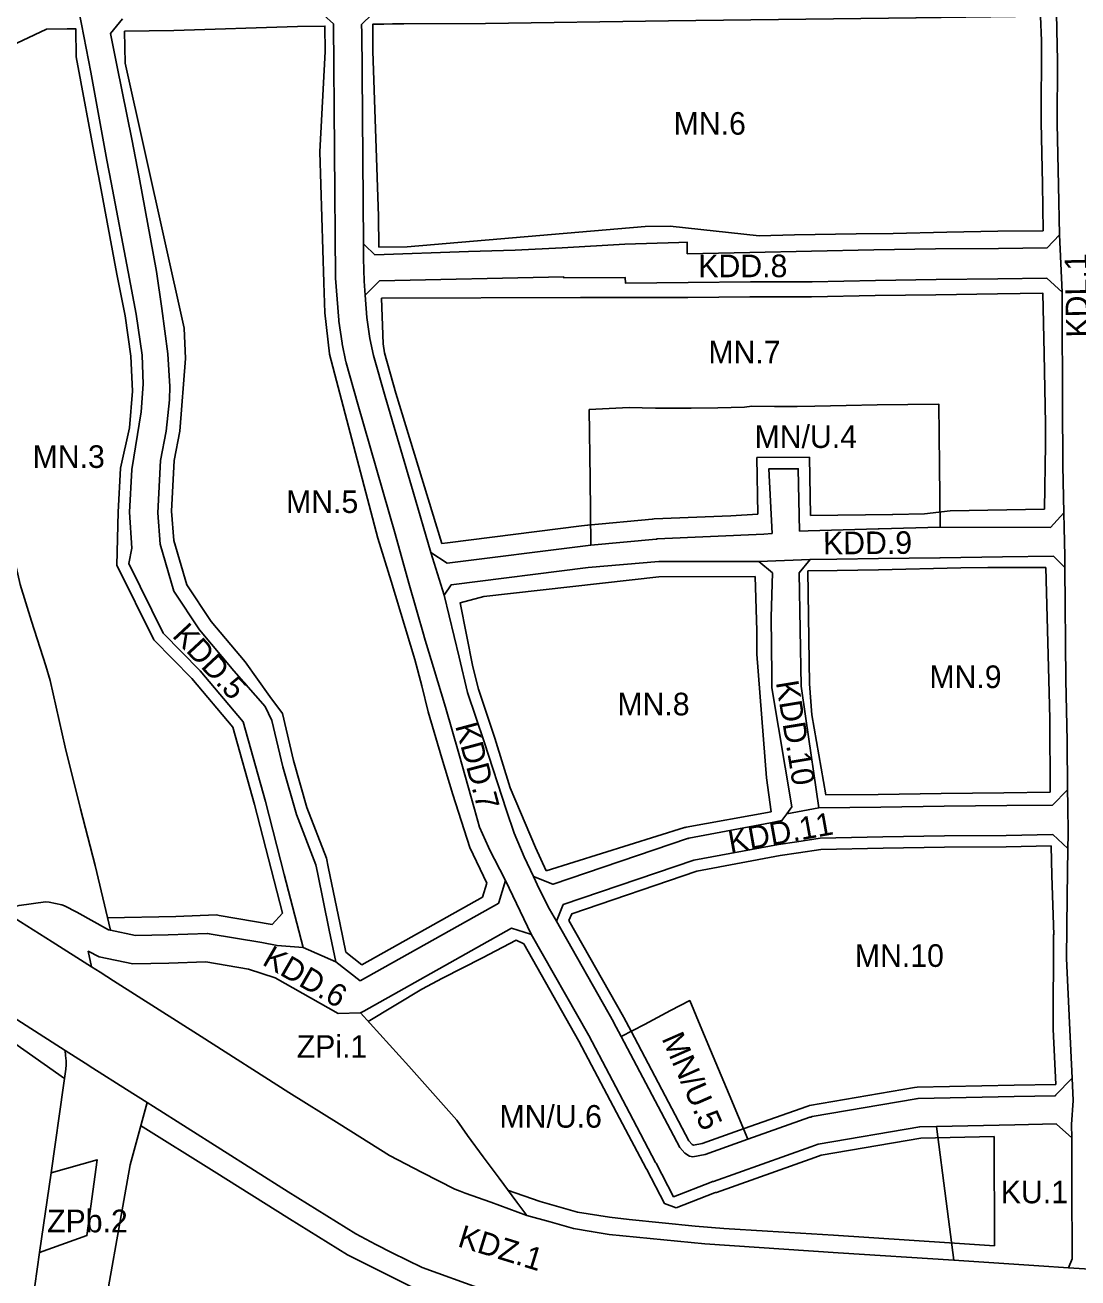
# Model space of a CAD drawing. Extents: x 7431080 to 7433370, y 5546450 to 5548428.
# Drawn here: x 7431280.3 to 7431653, y 5546842.9 to 5547286.3 of the extents above; entities that cross this region are included whole.
import ezdxf

# ---------------------------------------------------------------- set-up
doc = ezdxf.new("R2010")
doc.units = 0
for name, color, linetype in [('Linie Rozgraniczajace', 7, 'Continuous'), ('nieprzekraczalna linia zabudowy', 7, 'Continuous'), ('oznaczenia_przeznaczen', 7, 'Continuous')]:
    doc.layers.add(name, color=color, linetype=linetype)

msp = doc.modelspace()

# ---------------------------------------------------------------- linework, layer by layer
at = {"layer": 'Linie Rozgraniczajace'}
for p, q in [((7431503.72, 5547104.41), (7431480.6, 5547102.28)), ((7431541.78, 5547106.21), (7431544.79, 5547106.35)), ((7431428.7, 5547084.51), (7431424.02, 5547099.63)), ((7431544.96, 5547092.47), (7431540.08, 5547096.48)), ((7431546.99, 5546996.37), (7431553.47, 5546997.31)), ((7431285.51, 5546851.9), (7431289.57, 5546880.06)), ((7431457.94, 5546865.03), (7431445.21, 5546869.68)), ((7431457.94, 5546865.03), (7431454.46, 5546869.71))]:
    msp.add_line(p, q, dxfattribs=at)
for points in [[(7431390.34, 5546954.83), (7431378.8, 5546959.84), (7431372.11, 5546985.69), (7431365.42, 5547011.53), (7431357.5, 5547039.75), (7431342.29, 5547057.75), (7431329.25, 5547071.13), (7431317.06, 5547095.73), (7431318.2, 5547101.16), (7431317.29, 5547113.99), (7431318.15, 5547129.1), (7431321.47, 5547149.42), (7431322.16, 5547159.21), (7431321.76, 5547169.51), (7431319.7, 5547184.04), (7431316.79, 5547198.96), (7431310.88, 5547230.65), (7431309.31, 5547238.54), (7431303.61, 5547269.63), (7431300.27, 5547286.7), (7431297.91, 5547298.79)], [(7431400.09, 5547208.92), (7431399.5, 5547284.55), (7431399.48, 5547285.56), (7431399.47, 5547286.56), (7431403.16, 5547290.15), (7431404.45, 5547290.17), (7431443.28, 5547290.86), (7431508.06, 5547291.84), (7431608.94, 5547294.01), (7431608.98, 5547294.02), (7431609.02, 5547294.01), (7431640.93, 5547295.19), (7431645.37, 5547290.69)], [(7431646.11, 5547229.52), (7431645.64, 5547251.49), (7431645.76, 5547273.63), (7431645.5, 5547284.65), (7431645.37, 5547290.69), (7431645.25, 5547295.66)], [(7431398.93, 5546948.02), (7431390.34, 5546954.83), (7431388.02, 5546966.06), (7431383.82, 5546986.4), (7431383.27, 5546989.15), (7431376.44, 5547006.94), (7431371.63, 5547023.83), (7431367.75, 5547040.21), (7431365.33, 5547045.19), (7431354.3, 5547057.83), (7431342.1, 5547072.28), (7431333.03, 5547086.03), (7431328.12, 5547102.65), (7431327.33, 5547113.76), (7431328.29, 5547132.24), (7431330.29, 5547142.66), (7431331.52, 5547153.75), (7431331.59, 5547158.37), (7431330.89, 5547170.02), (7431328.77, 5547186.07), (7431326.91, 5547199.12), (7431320.7, 5547232.54), (7431318.12, 5547245.95), (7431312.95, 5547271.59), (7431310.62, 5547283.33), (7431314.85, 5547288.59)], [(7431411.39, 5547106.3), (7431398.16, 5547152.21), (7431393.99, 5547166.85), (7431393.97, 5547167.03), (7431393.91, 5547167.2), (7431392.59, 5547173.5), (7431392.56, 5547173.72), (7431392.54, 5547173.81), (7431391.42, 5547181.59), (7431391.4, 5547181.85), (7431391.39, 5547181.88), (7431390.2, 5547196.73), (7431390.22, 5547196.91), (7431390.18, 5547197.1), (7431389.5, 5547286.74), (7431386.05, 5547289.82), (7431403.16, 5547290.15)], [(7431310.57, 5546966), (7431305.12, 5546988.88), (7431299.98, 5547008.9), (7431294.56, 5547030.81), (7431289.26, 5547054.34), (7431287.66, 5547059.57), (7431282.62, 5547075.34), (7431278.58, 5547088.36), (7431271.49, 5547119.64), (7431263.97, 5547139.42), (7431263.95, 5547139.47), (7431244.76, 5547197.76), (7431231.95, 5547265)], [(7431648.18, 5547108.5), (7431648.07, 5547113.72), (7431647.72, 5547130.39), (7431647.54, 5547152.86), (7431647.49, 5547163.89), (7431647.43, 5547174.92), (7431647.4, 5547185.89), (7431647.38, 5547191.85), (7431646.45, 5547212.12), (7431646.11, 5547229.52)], [(7431492.6, 5547208.74), (7431511.75, 5547209.35), (7431514.75, 5547209.45), (7431514.73, 5547205.42), (7431536.92, 5547205.81), (7431558.76, 5547206.33), (7431580.81, 5547206.76), (7431602.65, 5547207.19), (7431624.84, 5547207.27), (7431642.14, 5547207.51), (7431646.45, 5547212.12)], [(7431400.71, 5547190.73), (7431400.32, 5547195.71), (7431400.11, 5547203.69), (7431400.09, 5547208.92)], [(7431400.09, 5547208.92), (7431400.51, 5547208.51), (7431404.16, 5547204.97), (7431437.36, 5547206.25), (7431453.84, 5547206.63), (7431470.45, 5547207.53), (7431492.6, 5547208.74)], [(7431400.71, 5547190.73), (7431400.91, 5547190.93), (7431405.79, 5547195.79), (7431471.03, 5547197.23)], [(7431515.07, 5547195.25), (7431492.88, 5547194.94), (7431492.72, 5547197.04), (7431471.07, 5547196.85), (7431471.03, 5547197.23)], [(7431515.07, 5547195.25), (7431537.09, 5547195.5), (7431558.9, 5547195.48), (7431581.31, 5547195.97), (7431602.88, 5547196.25), (7431624.71, 5547196.55), (7431641.99, 5547196.79), (7431647.38, 5547191.85)], [(7431424.02, 5547099.63), (7431417.73, 5547121.08), (7431407.79, 5547154.92), (7431403.66, 5547169.41), (7431402.41, 5547175.39), (7431401.35, 5547182.84), (7431400.71, 5547190.73)], [(7431480.6, 5547102.28), (7431480.34, 5547125.71), (7431480.07, 5547150.23), (7431487.1, 5547150.58), (7431494.13, 5547150.94), (7431498.83, 5547150.86), (7431503.53, 5547150.78)], [(7431503.53, 5547150.78), (7431509.81, 5547150.79), (7431516.09, 5547150.79), (7431525.54, 5547150.92), (7431534.98, 5547151.06), (7431537.56, 5547151.42), (7431545.61, 5547151.36), (7431553.65, 5547151.29), (7431559.93, 5547151.51), (7431570.94, 5547151.73), (7431581.95, 5547151.94), (7431592.84, 5547152.08), (7431603.74, 5547152.22), (7431604.02, 5547130.41), (7431604.3, 5547108.6)], [(7431554.49, 5547107.26), (7431554.03, 5547129.33), (7431543.62, 5547129.29), (7431544.79, 5547106.35)], [(7431648.07, 5547113.72), (7431643.36, 5547108.52)], [(7431411.39, 5547106.3), (7431416.14, 5547088.8), (7431421.57, 5547069.98), (7431421.61, 5547069.89), (7431421.61, 5547069.84), (7431424.93, 5547058.94), (7431429.14, 5547044.98), (7431433.92, 5547028.53), (7431439.46, 5547008.85), (7431441.25, 5547002.47), (7431444.34, 5546995.39), (7431444.51, 5546994.98), (7431450.36, 5546983.54), (7431459.52, 5546964.61)], [(7431503.72, 5547104.41), (7431503.83, 5547104.43), (7431504.14, 5547104.45), (7431541.78, 5547106.21)], [(7431554.49, 5547107.26), (7431557.5, 5547107.38)], [(7431643.36, 5547108.52), (7431604.3, 5547108.6), (7431582.62, 5547108.1), (7431582.49, 5547108.06), (7431582.34, 5547108.09), (7431557.5, 5547107.38)], [(7431648.36, 5547098.4), (7431648.18, 5547108.5)], [(7431424.02, 5547099.63), (7431429.76, 5547095.85), (7431478.7, 5547102.04), (7431480.6, 5547102.28)], [(7431428.7, 5547084.51), (7431431.12, 5547088.2), (7431479.68, 5547094.34), (7431504.72, 5547096.49), (7431540.08, 5547096.48), (7431558.22, 5547097.2)], [(7431555.03, 5547052.32), (7431554.39, 5547092.47), (7431558.22, 5547097.2), (7431567.72, 5547097.32), (7431582.38, 5547097.51), (7431604.15, 5547097.81), (7431604.19, 5547097.82), (7431604.24, 5547097.81), (7431626.37, 5547098.16), (7431644.41, 5547098.36)], [(7431644.41, 5547098.36), (7431648.39, 5547094.41)], [(7431649.38, 5547010.34), (7431649.33, 5547015.66), (7431649.17, 5547033.04), (7431648.67, 5547054.45), (7431648.39, 5547094.41), (7431648.36, 5547098.4)], [(7431550.01, 5547007.23), (7431551.79, 5547009.66), (7431544.67, 5547051.76), (7431544.62, 5547056.26), (7431544.45, 5547076.82), (7431544.96, 5547092.47)], [(7431460.29, 5546984.95), (7431456.98, 5546991.98), (7431453.47, 5547000.31), (7431450.77, 5547008.35), (7431442.84, 5547032.7), (7431436.97, 5547050.15), (7431433.97, 5547062.6), (7431428.7, 5547084.51)], [(7431555.03, 5547052.32), (7431556.7, 5547040.93), (7431561.36, 5547009.28), (7431583.28, 5547009.52), (7431605.62, 5547009.86), (7431627.84, 5547010.07), (7431644.01, 5547010.27), (7431649.33, 5547015.66)], [(7431561.36, 5547009.28), (7431550.01, 5547007.23), (7431548.22, 5547004.8), (7431544.15, 5547004.03)], [(7431649.55, 5546999.94), (7431649.38, 5547010.34)], [(7431460.29, 5546984.95), (7431467.18, 5546982.3), (7431467.25, 5546982.26), (7431514.79, 5546998.4), (7431515.02, 5546998.44), (7431515.32, 5546998.54), (7431544.15, 5547004.03)], [(7431561.73, 5546998.51), (7431553.47, 5546997.31)], [(7431649.48, 5546994.88), (7431644.12, 5546999.82), (7431627.57, 5546999.45), (7431605.73, 5546999.43), (7431583.97, 5546999.01), (7431561.73, 5546998.51)], [(7431650.03, 5546933.21), (7431648.99, 5546956.02), (7431649.25, 5546977.86), (7431649.27, 5546977.94), (7431649.25, 5546978.01), (7431649.48, 5546994.88), (7431649.55, 5546999.94)], [(7431468.43, 5546969.18), (7431470.87, 5546975.05), (7431517.1, 5546990.73), (7431546.99, 5546996.37)], [(7431468.43, 5546969.18), (7431466.02, 5546973.4), (7431462.31, 5546980.59), (7431462.34, 5546980.6), (7431460.29, 5546984.95)], [(7431450.36, 5546983.54), (7431447.99, 5546975.82), (7431448, 5546975.6), (7431398.93, 5546948.02)], [(7431262.98, 5546978.9), (7431272.03, 5546973.18), (7431278.23, 5546974.79), (7431287.58, 5546976.08), (7431288.88, 5546975.96), (7431293.32, 5546974.95), (7431294.31, 5546974.63), (7431298.65, 5546972.4)], [(7431272.03, 5546973.18), (7431289.89, 5546961.88), (7431303.9, 5546953.02), (7431306.93, 5546951.1), (7431311.64, 5546948.1)], [(7431378.8, 5546959.84), (7431369.61, 5546960.62), (7431364.21, 5546961.58), (7431345.54, 5546964.73), (7431344.94, 5546964.83), (7431330.95, 5546964.34), (7431319.48, 5546964.08), (7431310.57, 5546966), (7431309.93, 5546966.14), (7431298.65, 5546972.4)], [(7431491.33, 5546928.35), (7431488.63, 5546933.41), (7431488.58, 5546933.53), (7431468.43, 5546969.18)], [(7431399.08, 5546936.72), (7431400, 5546937.17), (7431400.26, 5546937.3), (7431452.53, 5546966.68), (7431459.29, 5546964.63), (7431459.52, 5546964.61), (7431479.84, 5546928.67), (7431494.3, 5546901.3)], [(7431399.08, 5546936.72), (7431391.14, 5546936.51), (7431368.86, 5546949.18), (7431359.43, 5546952.24), (7431344.28, 5546954.8), (7431331.24, 5546954.34), (7431318.53, 5546954.06), (7431306.63, 5546956.62), (7431302.74, 5546958.53), (7431303.9, 5546953.02)], [(7431304.29, 5546917.19), (7431301.62, 5546918.88), (7431294.52, 5546923.41), (7431276.16, 5546935.16), (7431257.57, 5546947.05), (7431250.17, 5546951.65), (7431242.76, 5546956.25), (7431240.39, 5546957.73)], [(7431311.64, 5546948.1), (7431342.65, 5546928.35), (7431373.66, 5546908.6), (7431391.53, 5546897.41), (7431409.39, 5546886.22), (7431420.95, 5546880.27), (7431432.51, 5546874.32), (7431434.32, 5546873.63), (7431436.13, 5546872.95), (7431445.21, 5546869.68)], [(7431536.21, 5546891.99), (7431529.54, 5546907.88), (7431522.98, 5546923.5), (7431519.29, 5546932.29), (7431515.59, 5546941.07), (7431508.85, 5546937.53), (7431499.57, 5546932.67), (7431491.33, 5546928.35)], [(7431454.46, 5546869.71), (7431448.13, 5546878.23), (7431442.53, 5546885.77), (7431436.93, 5546893.31), (7431433.23, 5546898.79), (7431416.16, 5546917.84), (7431399.08, 5546936.72)], [(7431650.87, 5546879.8), (7431650.84, 5546892.51), (7431650.79, 5546897.2), (7431651.28, 5546905.74), (7431650.92, 5546913.64), (7431650.03, 5546933.21)], [(7431536.21, 5546891.99), (7431521.07, 5546886.62), (7431516.7, 5546885.83), (7431515.54, 5546886.04), (7431513.91, 5546887.13), (7431512.06, 5546889.09), (7431491.33, 5546928.35)], [(7431294.52, 5546923.41), (7431294.7, 5546921.59), (7431294.89, 5546919.77), (7431294.86, 5546918.31), (7431294.83, 5546916.85), (7431293.98, 5546910.98)], [(7431304.29, 5546917.19), (7431316.25, 5546909.61), (7431323.53, 5546904.99)], [(7431650.92, 5546913.64), (7431645.11, 5546907.57), (7431645.05, 5546907.41), (7431630.47, 5546907.12), (7431596.46, 5546906.4), (7431596.42, 5546906.39), (7431596.37, 5546906.4), (7431595.72, 5546906.33), (7431558.97, 5546900.01), (7431558.5, 5546899.86), (7431558.15, 5546899.78), (7431536.21, 5546891.99)], [(7431289.57, 5546880.06), (7431293.98, 5546910.98)], [(7431323.53, 5546904.99), (7431317.61, 5546882.92), (7431306.12, 5546818.57), (7431300.78, 5546788.7), (7431299.43, 5546763.16), (7431301.94, 5546744.32)], [(7431521.53, 5546824.88), (7431511.67, 5546825.76), (7431482.02, 5546828.79), (7431466.14, 5546831.59), (7431451.55, 5546835.5), (7431441.76, 5546839.01), (7431420.92, 5546846.64), (7431410.25, 5546851.77), (7431404.56, 5546854.76), (7431397.4, 5546858.52), (7431373.5, 5546873.38), (7431325.81, 5546903.54), (7431323.53, 5546904.99)], [(7431558.5, 5546889.3), (7431524.03, 5546877.06), (7431523.72, 5546877), (7431523.25, 5546876.85), (7431523.22, 5546876.85), (7431509.9, 5546871.63), (7431503.76, 5546883.53), (7431503.53, 5546883.82), (7431494.3, 5546901.3)], [(7431558.5, 5546889.3), (7431561.09, 5546890.23), (7431597.04, 5546896.41), (7431602.92, 5546896.53), (7431630.67, 5546897.12), (7431645.35, 5546897.42), (7431645.39, 5546897.38), (7431650.84, 5546892.51)], [(7431602.92, 5546896.53), (7431606.36, 5546870.03), (7431609.06, 5546849.15)], [(7431289.57, 5546880.06), (7431305.82, 5546884.74), (7431302.24, 5546857.91), (7431285.51, 5546851.9)], [(7431650.89, 5546876.16), (7431650.87, 5546879.8)], [(7431649.72, 5546846.47), (7431651, 5546849.73), (7431650.89, 5546876.16)], [(7431568.09, 5546851.85), (7431520.94, 5546854.93), (7431487.04, 5546858.33), (7431480.78, 5546859.4), (7431474.51, 5546860.46), (7431466.21, 5546862.75), (7431457.94, 5546865.03)], [(7431276.17, 5546786.99), (7431280.14, 5546814.58), (7431283.78, 5546840.11), (7431285.51, 5546851.9)], [(7431568.09, 5546851.85), (7431609.06, 5546849.15), (7431628.52, 5546847.87)], [(7431628.52, 5546847.87), (7431639.16, 5546847.17), (7431649.72, 5546846.47), (7431664.61, 5546845.54), (7431664.34, 5546852.7), (7431666.92, 5546852.36), (7431684.77, 5546850.13)]]:
    msp.add_lwpolyline(points, dxfattribs=at)
at = {"layer": 'nieprzekraczalna linia zabudowy'}
for p, q in [((7431461.03, 5546995.24), (7431464.83, 5546986.95)), ((7431623.51, 5546854.31), (7431623.35, 5546892.96))]:
    msp.add_line(p, q, dxfattribs=at)
for points in [[(7431405.27, 5547104.72), (7431388.14, 5547169.89), (7431388.14, 5547169.89), (7431388.13, 5547169.96), (7431386.5, 5547184.49), (7431386.5, 5547184.49), (7431386.48, 5547184.57), (7431386.51, 5547184.46), (7431386.49, 5547184.52), (7431386.06, 5547195.11), (7431386.05, 5547195.18), (7431384.7, 5547241.52), (7431386.6, 5547276.98), (7431386.46, 5547285.98), (7431376.77, 5547285.83), (7431332.99, 5547284.38), (7431315.6, 5547284.15)], [(7431639.82, 5547289.54), (7431595.73, 5547288.84), (7431595.69, 5547288.85), (7431508.13, 5547287.84), (7431443.35, 5547286.86), (7431414.43, 5547286.74), (7431410.39, 5547286.82), (7431407.38, 5547286.63), (7431403.39, 5547286.61), (7431403.43, 5547277.15), (7431405.43, 5547218.72), (7431405.51, 5547207.73)], [(7431640.76, 5547213.56), (7431640.52, 5547229.97), (7431640.05, 5547251.99), (7431640.17, 5547280.75), (7431639.82, 5547289.54)], [(7431298.31, 5547285.02), (7431298.31, 5547285.02), (7431295.21, 5547285.02), (7431287.9, 5547284.87), (7431233.1, 5547259)], [(7431371.52, 5546972.01), (7431361.56, 5547010.49), (7431353.88, 5547037.83), (7431339.33, 5547055.06), (7431325.95, 5547068.79), (7431312.86, 5547095.2), (7431313.28, 5547113.96), (7431314.17, 5547129.54), (7431317.26, 5547143.79), (7431318.42, 5547156.82), (7431317.78, 5547169.15), (7431315.75, 5547183.38), (7431312.86, 5547198.21), (7431306.95, 5547229.89), (7431305.38, 5547237.78), (7431298.44, 5547275.05), (7431298.31, 5547285.02)], [(7431315.6, 5547284.15), (7431315.76, 5547272.9), (7431336.66, 5547179.05), (7431336.66, 5547179.05), (7431336.66, 5547179.05), (7431336.66, 5547179.05), (7431336.65, 5547179.12), (7431337.19, 5547168.37)], [(7431405.51, 5547207.73), (7431415.6, 5547207.81), (7431499.78, 5547215.02), (7431508.68, 5547215.17), (7431540.13, 5547211.8), (7431552.7, 5547212.09), (7431574.51, 5547212.46), (7431587.58, 5547212.59), (7431606.56, 5547213.06), (7431624.71, 5547213.34), (7431640.76, 5547213.56)], [(7431640.59, 5547191.4), (7431640.59, 5547191.4), (7431624.58, 5547191.18), (7431602.75, 5547190.88), (7431581.19, 5547190.6), (7431558.76, 5547190.11), (7431536.93, 5547190.13), (7431514.94, 5547189.88), (7431476.89, 5547189.96), (7431406.52, 5547189.68), (7431406.52, 5547189.68)], [(7431406.52, 5547189.68), (7431407.09, 5547173.46), (7431407.55, 5547170.37), (7431411.63, 5547156.03), (7431427.81, 5547102.88)], [(7431641.22, 5547114.96), (7431641.59, 5547137.86), (7431641.48, 5547145.16), (7431641.01, 5547170.14), (7431640.59, 5547191.4)], [(7431337.19, 5547168.37), (7431335.14, 5547142.59), (7431335.14, 5547142.59), (7431333.16, 5547132.28), (7431332.23, 5547114.32), (7431332.97, 5547103.89), (7431337.58, 5547088.26), (7431346.2, 5547075.2), (7431358.23, 5547060.96), (7431366.93, 5547048.7)], [(7431539.7, 5547113.24), (7431539.41, 5547133.27), (7431557.95, 5547133.35), (7431558.38, 5547112.72)], [(7431427.81, 5547102.88), (7431429.83, 5547103.09), (7431477.31, 5547109.09), (7431479.46, 5547109.36), (7431479.55, 5547109.36), (7431502.29, 5547111.46), (7431502.45, 5547111.49), (7431503.03, 5547111.53), (7431530.11, 5547112.7), (7431539.7, 5547113.24)], [(7431558.38, 5547112.72), (7431587.45, 5547113.12), (7431587.47, 5547113.13), (7431598.7, 5547113.36), (7431607.73, 5547114.37), (7431641.22, 5547114.97)], [(7431443.8, 5546982.63), (7431437.74, 5546995.28), (7431437.74, 5546995.28), (7431431.81, 5547014.03), (7431427.81, 5547026.89), (7431423.04, 5547043.31), (7431420.84, 5547052.46), (7431420.81, 5547052.49), (7431418.29, 5547061.84), (7431409.94, 5547089.56), (7431409.94, 5547089.56), (7431405.27, 5547104.72)], [(7431538.8, 5547091.15), (7431504.63, 5547091.09), (7431442.74, 5547084.06), (7431434.34, 5547081.84)], [(7431544.48, 5547007.89), (7431542.77, 5547019.87), (7431539.4, 5547063.69), (7431539.3, 5547071.94), (7431538.8, 5547091.15)], [(7431641.6, 5547094.33), (7431621.16, 5547094.36), (7431611.6, 5547094.24), (7431611.59, 5547094.24), (7431582.43, 5547093.51), (7431567.77, 5547093.32), (7431557.4, 5547093.19)], [(7431557.4, 5547093.19), (7431558.04, 5547053.16), (7431558.84, 5547042.17), (7431563.83, 5547013.84), (7431582.25, 5547014.04), (7431604.59, 5547014.38), (7431626.81, 5547014.59), (7431643.14, 5547014.79)], [(7431643.14, 5547014.79), (7431643.07, 5547040.84), (7431642.86, 5547050.06), (7431641.6, 5547094.33)], [(7431434.34, 5547081.84), (7431434.34, 5547081.84), (7431438.83, 5547059.21), (7431440.82, 5547051.26), (7431446.64, 5547033.96), (7431452.09, 5547016.33), (7431461.03, 5546995.24), (7431461.03, 5546995.24), (7431461.03, 5546995.24)], [(7431366.93, 5547048.7), (7431371.43, 5547042.73), (7431375.39, 5547026.01), (7431380.13, 5547009.38), (7431387.02, 5546991.44), (7431387.63, 5546988.37), (7431391.83, 5546968.04), (7431393.85, 5546958.23), (7431399.57, 5546953.7)], [(7431464.83, 5546986.95), (7431513.8, 5547002.29), (7431514.04, 5547002.33), (7431514.31, 5547002.42), (7431544.47, 5547007.89)], [(7431643.58, 5546995.81), (7431627.62, 5546995.45), (7431605.77, 5546995.43), (7431584.05, 5546995.01), (7431562.06, 5546994.52), (7431554.15, 5546993.37), (7431554.1, 5546993.36), (7431547.65, 5546992.42), (7431518.12, 5546986.85), (7431473.87, 5546971.84), (7431472.87, 5546969.45)], [(7431645.13, 5546911.41), (7431644.24, 5546930.98), (7431644.34, 5546964.4), (7431644.45, 5546964.36), (7431643.77, 5546985.34), (7431643.58, 5546995.81)], [(7431399.57, 5546953.7), (7431442.29, 5546977.71), (7431443.8, 5546982.63)], [(7431309.54, 5546970.33), (7431333.72, 5546970.88), (7431348.09, 5546971.38), (7431349.09, 5546971.21), (7431367.85, 5546968.05), (7431371.52, 5546972.01)], [(7431472.87, 5546969.45), (7431492.18, 5546935.29), (7431492.25, 5546935.13), (7431494.83, 5546930.29)], [(7431490.76, 5546899.43), (7431476.33, 5546926.75), (7431456.86, 5546961.19), (7431454.12, 5546962.48), (7431442.23, 5546956.23), (7431428.14, 5546949.04), (7431420.83, 5546945.17), (7431401.84, 5546933.67)], [(7431294.35, 5546913.52), (7431250.99, 5546943.91), (7431228.74, 5546954.88)], [(7431494.84, 5546930.28), (7431515.34, 5546891.44), (7431516.51, 5546890.2), (7431516.91, 5546889.93), (7431520.04, 5546890.5), (7431534.87, 5546895.76)], [(7431534.87, 5546895.76), (7431557.03, 5546903.63), (7431557.44, 5546903.72), (7431558.02, 5546903.91), (7431595.17, 5546910.29), (7431596.09, 5546910.39), (7431630.39, 5546911.12), (7431645.13, 5546911.41)], [(7431577.62, 5546812.63), (7431567.3, 5546813.26), (7431544.99, 5546815), (7431510.72, 5546817.85), (7431480.01, 5546820.97), (7431465.08, 5546823.54), (7431448.61, 5546827.9), (7431417.83, 5546839.36), (7431394.45, 5546851.12), (7431373.94, 5546863.8), (7431347.31, 5546880.59), (7431321.23, 5546896.87)], [(7431510.79, 5546867.68), (7431506.62, 5546869.26), (7431500.38, 5546881.35), (7431500.17, 5546881.62), (7431490.76, 5546899.43)], [(7431623.35, 5546892.96), (7431597.42, 5546892.42), (7431562.11, 5546886.35), (7431559.85, 5546885.54)], [(7431559.84, 5546885.53), (7431525.09, 5546873.19), (7431524.71, 5546873.12), (7431524.43, 5546873.03), (7431510.79, 5546867.68)], [(7431451.12, 5546873.96), (7431462.67, 5546869.93), (7431475.93, 5546866.17), (7431487.25, 5546864.38), (7431494.17, 5546863.6), (7431517.57, 5546861.24), (7431527.66, 5546860.46), (7431543.19, 5546859.5), (7431566.55, 5546858.06)], [(7431566.55, 5546858.06), (7431607.52, 5546855.36), (7431623.51, 5546854.31)]]:
    msp.add_lwpolyline(points, dxfattribs=at)

# ---------------------------------------------------------------- texts
at = {"layer": 'oznaczenia_przeznaczen'}
for s, p in [('MN.6', (7431509.92, 5547247.54)), ('MN.6', (7431509.92, 5547247.54)), ('KDD.8', (7431518.66, 5547197.1)), ('KDD.8', (7431518.66, 5547197.1)), ('MN.7', (7431522.21, 5547166.59)), ('MN/U.4', (7431538.55, 5547136.67)), ('MN.3', (7431283.02, 5547129.6)), ('MN.3', (7431283.02, 5547129.6)), ('MN.3', (7431283.02, 5547129.6)), ('MN.5', (7431372.73, 5547113.65)), ('MN.9', (7431600.43, 5547051.69)), ('MN.9', (7431600.43, 5547051.69)), ('MN.8', (7431490, 5547042.03)), ('MN.10', (7431574.05, 5546953)), ('ZPi.1', (7431376.51, 5546920.83)), ('ZPi.1', (7431376.51, 5546920.83)), ('ZPi.1', (7431376.51, 5546920.83)), ('MN/U.6', (7431448.27, 5546896.1)), ('MN/U.6', (7431448.27, 5546896.1)), ('MN/U.6', (7431448.27, 5546896.1)), ('KU.1', (7431625.72, 5546869.34)), ('KU.1', (7431625.72, 5546869.34)), ('KU.1', (7431625.72, 5546869.34)), ('ZPb.2', (7431288.16, 5546859.07)), ('ZPb.2', (7431288.16, 5546859.07)), ('ZPb.2', (7431288.16, 5546859.07)), ('ZPb.2', (7431288.16, 5546859.07))]:
    msp.add_text(s, height=8, dxfattribs=at).set_placement(p)
for s, rotation, p in [('KDL.1', 91.241, (7431656.9, 5547175.84)), ('KDD.9', 0.4425, (7431562.82, 5547098.97)), ('KDD.9', 0.4425, (7431562.82, 5547098.97)), ('KDD.5', 312.9835, (7431332.13, 5547069.99)), ('KDD.10', 279.2952, (7431546.06, 5547053.74)), ('KDD.7', 284.9814, (7431432.55, 5547038.35)), ('KDD.11', 10.19, (7431529.96, 5546993.34)), ('KDD.11', 10.19, (7431529.96, 5546993.34)), ('KDD.6', 329.9703, (7431363.91, 5546954.01)), ('MN/U.5', 293.6592, (7431505.56, 5546927.68)), ('MN/U.5', 293.6592, (7431505.56, 5546927.68)), ('MN/U.5', 293.6592, (7431505.56, 5546927.68)), ('KDZ.1', 342.8908, (7431433.1, 5546854.18)), ('KDZ.1', 342.8908, (7431433.1, 5546854.18)), ('KDZ.1', 342.8908, (7431433.1, 5546854.18))]:
    msp.add_text(s, height=8, rotation=rotation, dxfattribs=at).set_placement(p)

doc.saveas('drawing.dxf')
